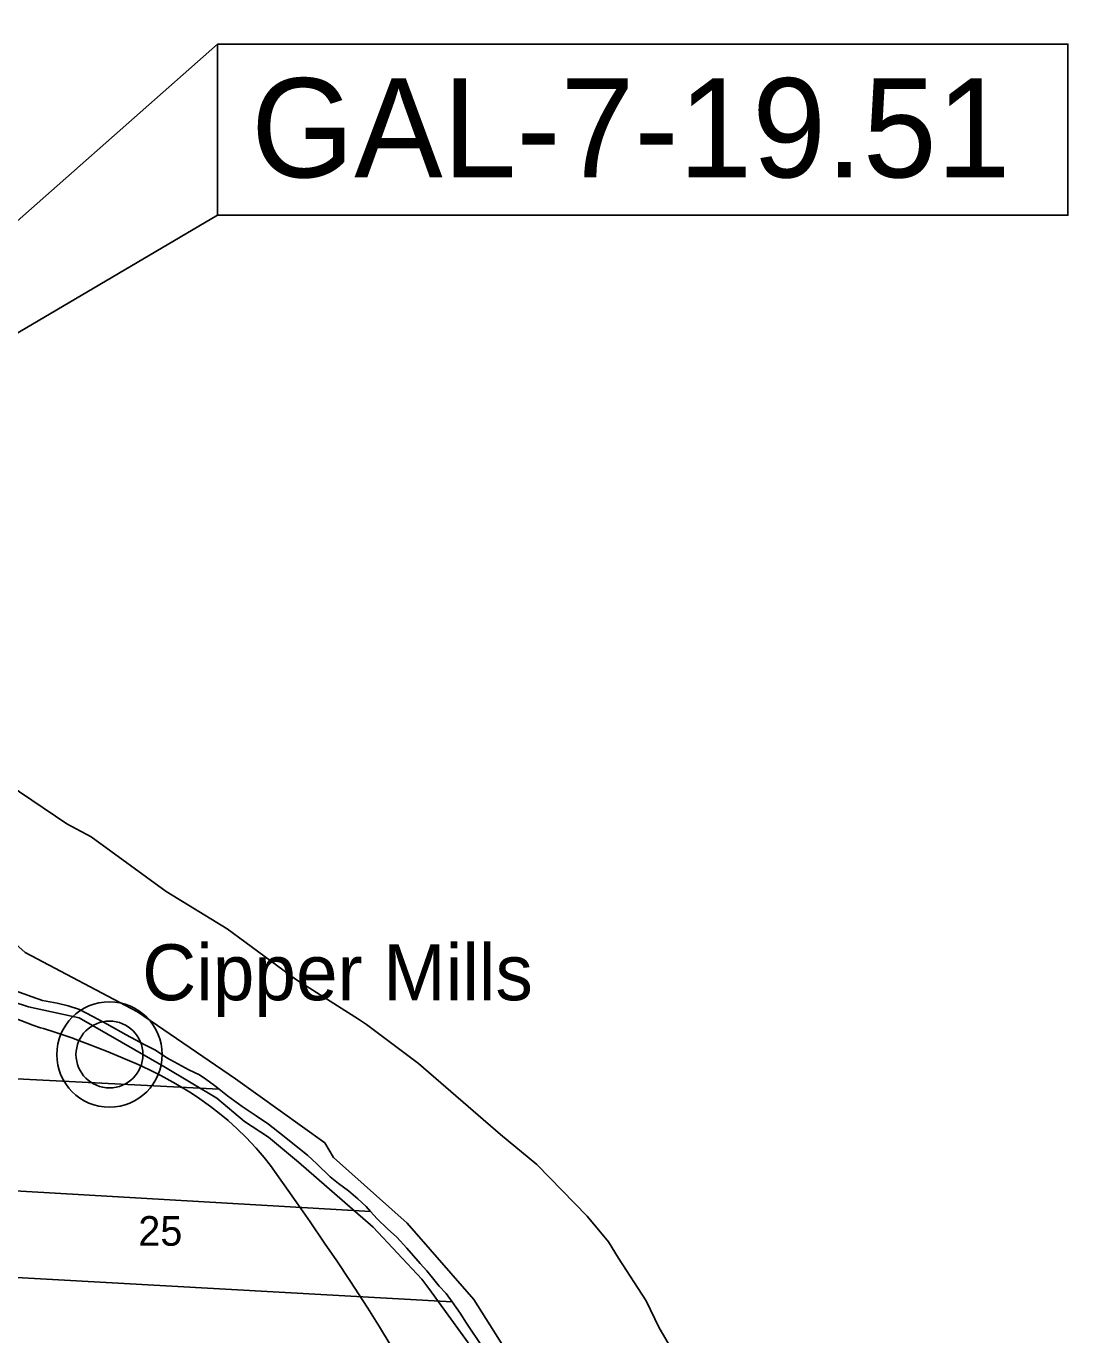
# Model space of a CAD drawing. Extents: x 21.4 to 65.3, y 4 to 26.
# Drawn here: x 27.421 to 28.891, y 20.4 to 22.248 of the extents above; entities that cross this region are included whole.
import ezdxf

# ---------------------------------------------------------------- set-up
doc = ezdxf.new("R2010")
doc.units = 0
for name, color, linetype in [('Default', 7, 'Continuous'), ('GM_X_Major_River', 7, 'Continuous'), ('GM_X_Section', 7, 'Continuous'), ('GM_X_Section_Text', 7, 'Continuous'), ('GM_X_State_Route', 7, 'Continuous'), ('GM_X_Unincorporated', 7, 'Continuous'), ('GM_X_Unincorporated_Location', 7, 'Continuous'), ('GM_X_Unincorporated_Text', 7, 'Continuous'), ('SH_Cut_Line', 7, 'Continuous'), ('TX_P_1', 7, 'Continuous')]:
    doc.layers.add(name, color=color, linetype=linetype)

msp = doc.modelspace()

# ---------------------------------------------------------------- linework, layer by layer
at = {"layer": 'Default'}
msp.add_lwpolyline([(28.1702, 20.2638), (28.0527, 20.4505), (27.9586, 20.5583), (27.8546, 20.6506), (27.8422, 20.6714), (27.7163, 20.7618), (27.578, 20.8563), (27.4195, 20.94), (27.2824, 21.0623), (27.2266, 21.087), (27.1713, 21.1261), (27.0325, 21.1315), (26.8527, 21.1433), (26.379, 21.1689), (26.3338, 20.4317), (26.0076, 20.4475), (25.9047, 20.4519), (25.9039, 20.4514), (25.9007, 20.45), (25.896, 20.4488), (25.89, 20.4485), (25.878, 20.4484), (25.869, 20.4484)], dxfattribs=at)
at = {"layer": 'GM_X_Major_River'}
for points in [[(28.3665, 20.3213), (28.3144, 20.4103), (28.2961, 20.4482), (28.2569, 20.5088), (28.2428, 20.5319), (28.2128, 20.5678), (28.1418, 20.6408), (28.0903, 20.6831), (27.9746, 20.7836), (27.901, 20.8384), (27.89, 20.8463), (27.801, 20.9025), (27.7047, 20.9735), (27.6183, 21.0263), (27.5125, 21.1033), (27.478, 21.1221), (27.3279, 21.2229)], [(27.4011, 20.8709), (27.4242, 20.8634), (27.4957, 20.8481), (27.6151, 20.7791), (27.6897, 20.7346), (27.7292, 20.7014), (27.7629, 20.6795), (27.805, 20.644), (27.9108, 20.5526), (27.9792, 20.4788), (27.9894, 20.4659), (28.0651, 20.3615)]]:
    msp.add_lwpolyline(points, dxfattribs=at)
at = {"layer": 'GM_X_Section'}
for points in [[(27.3892, 20.763), (27.3965, 20.8901), (27.4059, 20.8863), (27.4291, 20.8776), (27.4439, 20.8724), (27.4643, 20.8687), (27.4799, 20.8649), (27.4962, 20.8597), (27.5148, 20.8499), (27.5349, 20.839), (27.5619, 20.8239), (27.5884, 20.81), (27.6032, 20.8021), (27.6192, 20.7915), (27.6503, 20.7746), (27.6655, 20.7675), (27.6742, 20.7614), (27.6868, 20.7524), (27.6933, 20.7471)], [(27.3892, 20.763), (27.6933, 20.7471), (27.705, 20.7377), (27.7259, 20.723), (27.7456, 20.7098), (27.7631, 20.6977), (27.7848, 20.6803), (27.8045, 20.6649), (27.8178, 20.6539), (27.8311, 20.6419), (27.8498, 20.6234), (27.8615, 20.6139), (27.8756, 20.6037), (27.8889, 20.5924), (27.9007, 20.5815), (27.907, 20.5744), (27.3801, 20.6051)], [(27.907, 20.5744), (27.9163, 20.5641), (27.9311, 20.5501), (27.944, 20.5384), (27.9581, 20.5226), (27.9771, 20.501), (27.9866, 20.4908), (27.9965, 20.4784), (28.0037, 20.4693), (28.0136, 20.4587), (28.0222, 20.4469), (27.3731, 20.4834), (27.3801, 20.6051)], [(27.3731, 20.4834), (28.0222, 20.4469), (28.0334, 20.4311), (28.0422, 20.4171), (28.0647, 20.3839), (28.073, 20.3722), (28.0829, 20.3589), (28.0906, 20.3484), (28.1023, 20.3397), (27.6101, 20.3651), (27.367, 20.3777)]]:
    msp.add_lwpolyline(points, close=True, dxfattribs=at)
at = {"layer": 'GM_X_State_Route'}
for points in [[(27.445, 20.8327), (27.4412, 20.8339), (27.43, 20.8377), (27.4131, 20.8441), (27.4021, 20.8484), (27.3921, 20.8527)], [(27.9346, 20.3867), (27.9197, 20.4118), (27.9033, 20.4381), (27.8779, 20.4772), (27.8592, 20.5051), (27.842, 20.53), (27.8215, 20.5598), (27.8051, 20.5835), (27.7908, 20.6043), (27.7772, 20.6236), (27.7655, 20.6396), (27.7567, 20.6508), (27.7453, 20.6639), (27.7309, 20.6793), (27.7185, 20.6915), (27.7057, 20.7032), (27.6938, 20.7131), (27.681, 20.7229), (27.6628, 20.7359), (27.6519, 20.743), (27.6322, 20.7547), (27.6111, 20.7665), (27.5951, 20.7747), (27.5787, 20.7822), (27.5364, 20.8), (27.5074, 20.8112), (27.4923, 20.8169), (27.4865, 20.8191), (27.4795, 20.8216), (27.4696, 20.825), (27.4613, 20.8276), (27.445, 20.8327)]]:
    msp.add_lwpolyline(points, dxfattribs=at)
at = {"layer": 'GM_X_Unincorporated'}
for radius in [0.0744, 0.0472]:
    msp.add_circle((27.5383, 20.7962), radius, dxfattribs=at)
at = {"layer": 'GM_X_Unincorporated_Location'}
msp.add_line((27.5383, 20.7962), (27.5383, 20.7962), dxfattribs=at)
at = {"layer": 'SH_Cut_Line'}
msp.add_lwpolyline([(28.1702, 20.2638), (28.0527, 20.4505), (27.9586, 20.5583), (27.8546, 20.6506), (27.8422, 20.6714), (27.7163, 20.7618), (27.578, 20.8563), (27.4195, 20.94), (27.2824, 21.0623), (27.2266, 21.087), (27.1713, 21.1261), (27.125, 21.1713), (27.0715, 21.2402), (26.9875, 21.3717), (26.9395, 21.4715), (26.8968, 21.6757), (26.8802, 21.8461), (26.8806, 21.8662), (26.8662, 22.382)], dxfattribs=at)
at = {"layer": 'TX_P_1'}
for points in [[(27.691, 22.2228), (26.8702, 21.498), (27.691, 21.9812)], [(27.691, 22.2228), (28.8914, 22.2228), (28.8914, 21.9812), (27.691, 21.9812)]]:
    msp.add_lwpolyline(points, close=True, dxfattribs=at)

# ---------------------------------------------------------------- texts
at = {"layer": 'GM_X_Section_Text'}
msp.add_text('25', height=0.04186, rotation=0, dxfattribs=at).set_placement((27.579, 20.5262))
at = {"layer": 'GM_X_Unincorporated_Text'}
msp.add_text('Cipper Mills', height=0.078977, rotation=0, dxfattribs=at).set_placement((27.5845, 20.8728))
at = {"layer": 'TX_P_1'}
msp.add_text('GAL-7-19.51', height=0.14, dxfattribs=at).set_placement((27.7383, 22.0346))

doc.saveas('drawing.dxf')
